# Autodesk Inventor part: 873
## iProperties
Author: Vincent Molino
Shininess: 100.0
Angle Display Precision: 2
Document Length Units: 11272
Document Angle Units: 11286
Document Time Units: 11279
Document Mass Units: 11290
Document Length Units Precision: 3
Document Angle Units Precision: 2
Compacted: True
PropertySet Name: _Private Model Information
Created: 2002-05
Part Number: 873
Document SubType Name: Modeling
Designer: Vincent Molino
Control State: 0
Master: False
Checked Out: False
PropertySet Name: Design Tracking Control
Density: 0.0
Volumn: 0.0
Area: 0.0
PropertySet Name: Model Information
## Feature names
1. Extrusion1
2. Extrusion2
